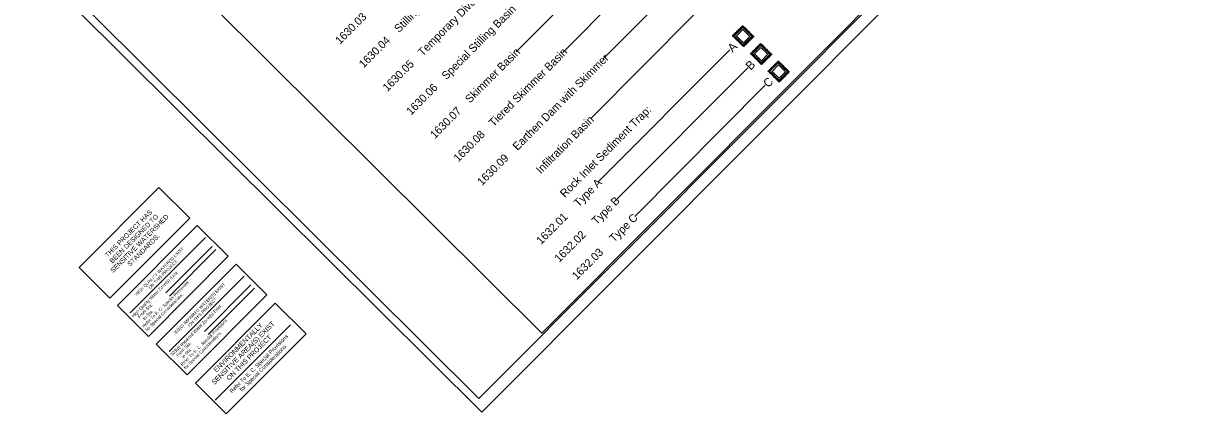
# Model space of a CAD drawing. Extents: x 1489771 to 1495672, y 500348 to 506262.
# Drawn here: x 1489771 to 1495672, y 500348 to 502337 of the extents above; entities that cross this region are included whole.
import ezdxf

# ---------------------------------------------------------------- set-up
doc = ezdxf.new("R2010")
doc.units = 0
for name, color, linetype in [('Old_Level_1', 7, 'Continuous'), ('Old_Level_12', 7, 'Continuous'), ('Scratch_Level_4', 7, 'Continuous'), ('Sheet Plot Border Inside CELL', 7, 'Continuous')]:
    doc.layers.add(name, color=color, linetype=linetype)

msp = doc.modelspace()

# ---------------------------------------------------------------- linework, layer by layer
at = {"layer": 'Old_Level_1'}
for p, q in [((1492277.2, 502190.4), (1492822.6, 502739.5)), ((1492514, 502187.4), (1492943.2, 502619.5)), ((1492722.3, 502156.2), (1493063.4, 502499.7)), ((1492658.6, 501853.6), (1493182.1, 502380.6)), ((1492695, 501528.4), (1493363.2, 502201.1)), ((1492786.5, 501436.8), (1493454.9, 502109.8)), ((1492880.1, 501352.6), (1493544.1, 502021)), ((1492407.6, 500758.5), (1492407.6, 500758.5))]:
    msp.add_line(p, q, dxfattribs=at)
for points in [[(1493352.5, 506178.3), (1490172.1, 502984.8), (1492407.6, 500758.5), (1495587.9, 503952.1)], [(1493397.6, 502271.2), (1493430.4, 502304.2), (1493465.7, 502268.9), (1493433.6, 502236.5)], [(1493489.3, 502179.9), (1493522, 502212.9), (1493557, 502178.2), (1493525.3, 502145.2)], [(1493578.3, 502091.2), (1493611.1, 502124), (1493646.6, 502088.8), (1493614.4, 502056.4)]]:
    msp.add_lwpolyline(points, close=True, dxfattribs=at)
for centre in [(1493382.5, 502272.3), (1493389.2, 502279.1), (1493389.8, 502265.1), (1493396, 502285.9), (1493402.7, 502292.7), (1493409.5, 502299.4), (1493416.2, 502306.2), (1493423, 502313), (1493429.7, 502319.7), (1493437, 502312.5), (1493444.3, 502305.2), (1493451.6, 502297.9), (1493458.9, 502290.7), (1493466.2, 502283.4), (1493473.5, 502276.1), (1493480.8, 502268.8), (1493397.1, 502257.8), (1493404.4, 502250.5), (1493411.7, 502243.3), (1493419, 502236), (1493426.3, 502228.7), (1493433.6, 502221.5), (1493440.3, 502228.2), (1493447.1, 502235), (1493453.8, 502241.8), (1493460.6, 502248.5), (1493467.3, 502255.3), (1493474.1, 502262.1), (1493500.9, 502208.4), (1493507.6, 502215.2), (1493514.4, 502222), (1493521.1, 502228.8), (1493528.4, 502221.5), (1493535.7, 502214.2), (1493543, 502206.9), (1493473.9, 502181.4), (1493480.7, 502188.1), (1493481.2, 502174.1), (1493487.4, 502194.9), (1493488.5, 502166.8), (1493494.2, 502201.7), (1493495.8, 502159.6), (1493503.1, 502152.3), (1493545.3, 502150.8), (1493550.3, 502199.7), (1493552, 502157.6), (1493557.6, 502192.4), (1493558.7, 502164.3), (1493564.9, 502185.1), (1493565.5, 502171.1), (1493572.2, 502177.9), (1493510.4, 502145), (1493517.7, 502137.8), (1493525, 502130.5), (1493531.8, 502137.3), (1493538.5, 502144), (1493563.3, 502092.3), (1493570.1, 502099.1), (1493576.8, 502105.8), (1493583.5, 502112.6), (1493590.3, 502119.4), (1493597, 502126.1), (1493603.8, 502132.9), (1493610.5, 502139.7), (1493617.8, 502132.4), (1493625.1, 502125.1), (1493632.4, 502117.9), (1493639.7, 502110.6), (1493647, 502103.3), (1493654.3, 502096.1), (1493661.6, 502088.8), (1493570.6, 502085), (1493577.9, 502077.8), (1493585.2, 502070.5), (1493592.5, 502063.2), (1493599.8, 502055.9), (1493607.1, 502048.7), (1493614.4, 502041.4), (1493621.1, 502048.2), (1493627.9, 502054.9), (1493634.6, 502061.7), (1493641.4, 502068.5), (1493648.1, 502075.3), (1493654.9, 502082)]:
    msp.add_ellipse(centre, major_axis=(3.01, -3), ratio=0.927398, dxfattribs=at)
at = {"layer": 'Old_Level_12'}
msp.add_lwpolyline([(1492102.5, 500356.3), (1495671.9, 503940.6), (1493340.6, 506262.2), (1489771.2, 502678)], close=True, dxfattribs=at)
at = {"layer": 'Scratch_Level_4'}
for p, q in [((1490496.5, 500963.3), (1490732, 501199.8)), ((1490514.5, 500947.5), (1490750.1, 501183.9)), ((1490693.4, 500767.1), (1490929, 501003.6)), ((1490711.5, 500751.3), (1490947, 500987.8))]:
    msp.add_line(p, q, dxfattribs=at)
for points in [[(1490054.9, 501093.1), (1490460.7, 501500.6), (1490617.8, 501344.2), (1490212, 500936.7)], [(1490250.4, 500898.5), (1490656.2, 501306), (1490813.2, 501149.6), (1490407.4, 500742.1)], [(1490447.3, 500702.3), (1490853.2, 501109.8), (1491010.2, 500953.4), (1490604.4, 500545.9)], [(1490646.4, 500504), (1491052.2, 500911.6), (1491209.3, 500755.1), (1490803.5, 500347.6)]]:
    msp.add_lwpolyline(points, close=True, dxfattribs=at)
for points in [[(1490316.7, 500862.2), (1490317.5, 500863), (1490697.6, 501244.7)], [(1490513.7, 500666.1), (1490514.4, 500666.8), (1490894.6, 501048.6)], [(1490748.4, 500417.4), (1490749.1, 500418.1), (1491129.4, 500799.9)]]:
    msp.add_lwpolyline(points, dxfattribs=at)
at = {"layer": 'Sheet Plot Border Inside CELL'}
msp.add_lwpolyline([(1492087.5, 500426.4), (1495619.8, 503973.4), (1493373.6, 506210.2), (1489841.3, 502663.3)], close=True, dxfattribs=at)

# ---------------------------------------------------------------- texts
at = {"layer": 'Old_Level_1'}
for s, height, p in [('Stilling Basin', 40.761, (1491681.6, 502285.9)), ('Temporary Diversion', 40.777, (1491802.2, 502165.9)), ('1630.03', 40.71, (1491381.7, 502225.9)), ('Special Stilling Basin', 40.761, (1491922.7, 502045.8)), ('1630.04', 40.71, (1491502.2, 502105.9)), ('A', 42.9, (1493378.4, 502186)), ('1630.05', 40.71, (1491622.8, 501985.8)), ('Skimmer Basin', 40.761, (1492042.3, 501926.8)), ('Tiered Skimmer Basin', 40.761, (1492162.8, 501806.7)), ('Earthen Dam with Skimmer', 40.761, (1492284, 501685.7)), ('B', 42.9, (1493470.1, 502094.6)), ('C', 42.9, (1493559.3, 502005.9)), ('1630.06', 40.71, (1491743.3, 501865.8)), ('1630.07', 40.71, (1491863.9, 501745.7)), ('Infiltration Basin', 40.761, (1492402.8, 501566.9)), ('Rock Inlet Sediment Trap:', 40.704, (1492524.7, 501446.3)), ('1630.08', 40.71, (1491983.4, 501626.6)), ('1630.09', 40.71, (1492104, 501506.6)), (' Type A', 40.76, (1492583.9, 501387.4)), (' Type B', 40.76, (1492675.6, 501296.1)), ('1632.01', 40.71, (1492404.5, 501207.3)), (' Type C', 40.76, (1492764.7, 501207.3)), ('1632.02', 40.71, (1492496.2, 501116)), ('1632.03', 40.71, (1492585.3, 501027.2))]:
    msp.add_text(s, height=height, rotation=45.11863, dxfattribs=at).set_placement(p)
at = {"layer": 'Scratch_Level_4'}
for s, height, p in [('THIS PROJECT HAS', 24.498, (1490201.3, 501142.1)), ('BEEN DESIGNED TO ', 24.498, (1490224.6, 501112.3)), ('SENSITIVE WATERSHED', 24.498, (1490229.1, 501063.6)), ('STANDARDS.', 24.5, (1490314.7, 501096.4)), ('    HIGH QUALITY WATER(S) EXIST', 15.923, (1490331.2, 500929.1)), ('                ON THIS PROJECT', 15.923, (1490348.3, 500912.1)), ('High Quality Water Zone(s) Exist', 15.923, (1490332.2, 500836.9)), ('Refer To E. C. Special Provisions', 15.923, (1490384.7, 500784.6)), ('    303(d) IMPAIRED WATER(S) EXIST', 15.923, (1490528.2, 500733)), ('for Special Considerations.', 15.923, (1490402, 500767.3)), ('                 ON THIS PROJECT', 15.923, (1490545.2, 500716)), ('   From Sta.                      ', 15.923, (1490349.6, 500819.6)), ('     to Sta.', 15.923, (1490367.3, 500801.9)), ('303(d) Impaired Water Zone(s) Exist', 15.923, (1490528.8, 500641)), ('Refer To E. C. Special Provisions', 15.923, (1490580.1, 500590)), ('SENSITIVE AREA(S) EXIST', 24.879, (1490743.7, 500493.9)), ('ENVIRONMENTALLY ', 24.879, (1490753.2, 500556.7)), ('for Special Considerations.', 15.923, (1490597.1, 500573)), ('ON THIS PROJECT', 24.879, (1490818.6, 500515.7)), ('Refer To E. C. Special Provisions', 19.903, (1490832.4, 500451.2)), ('   From Sta.                      ', 15.923, (1490545.9, 500624)), ('for Special Considerations.', 19.903, (1490883.7, 500460)), ('     to Sta.', 15.923, (1490563, 500607))]:
    msp.add_text(s, height=height, rotation=45.11863, dxfattribs=at).set_placement(p)

doc.saveas('drawing.dxf')
